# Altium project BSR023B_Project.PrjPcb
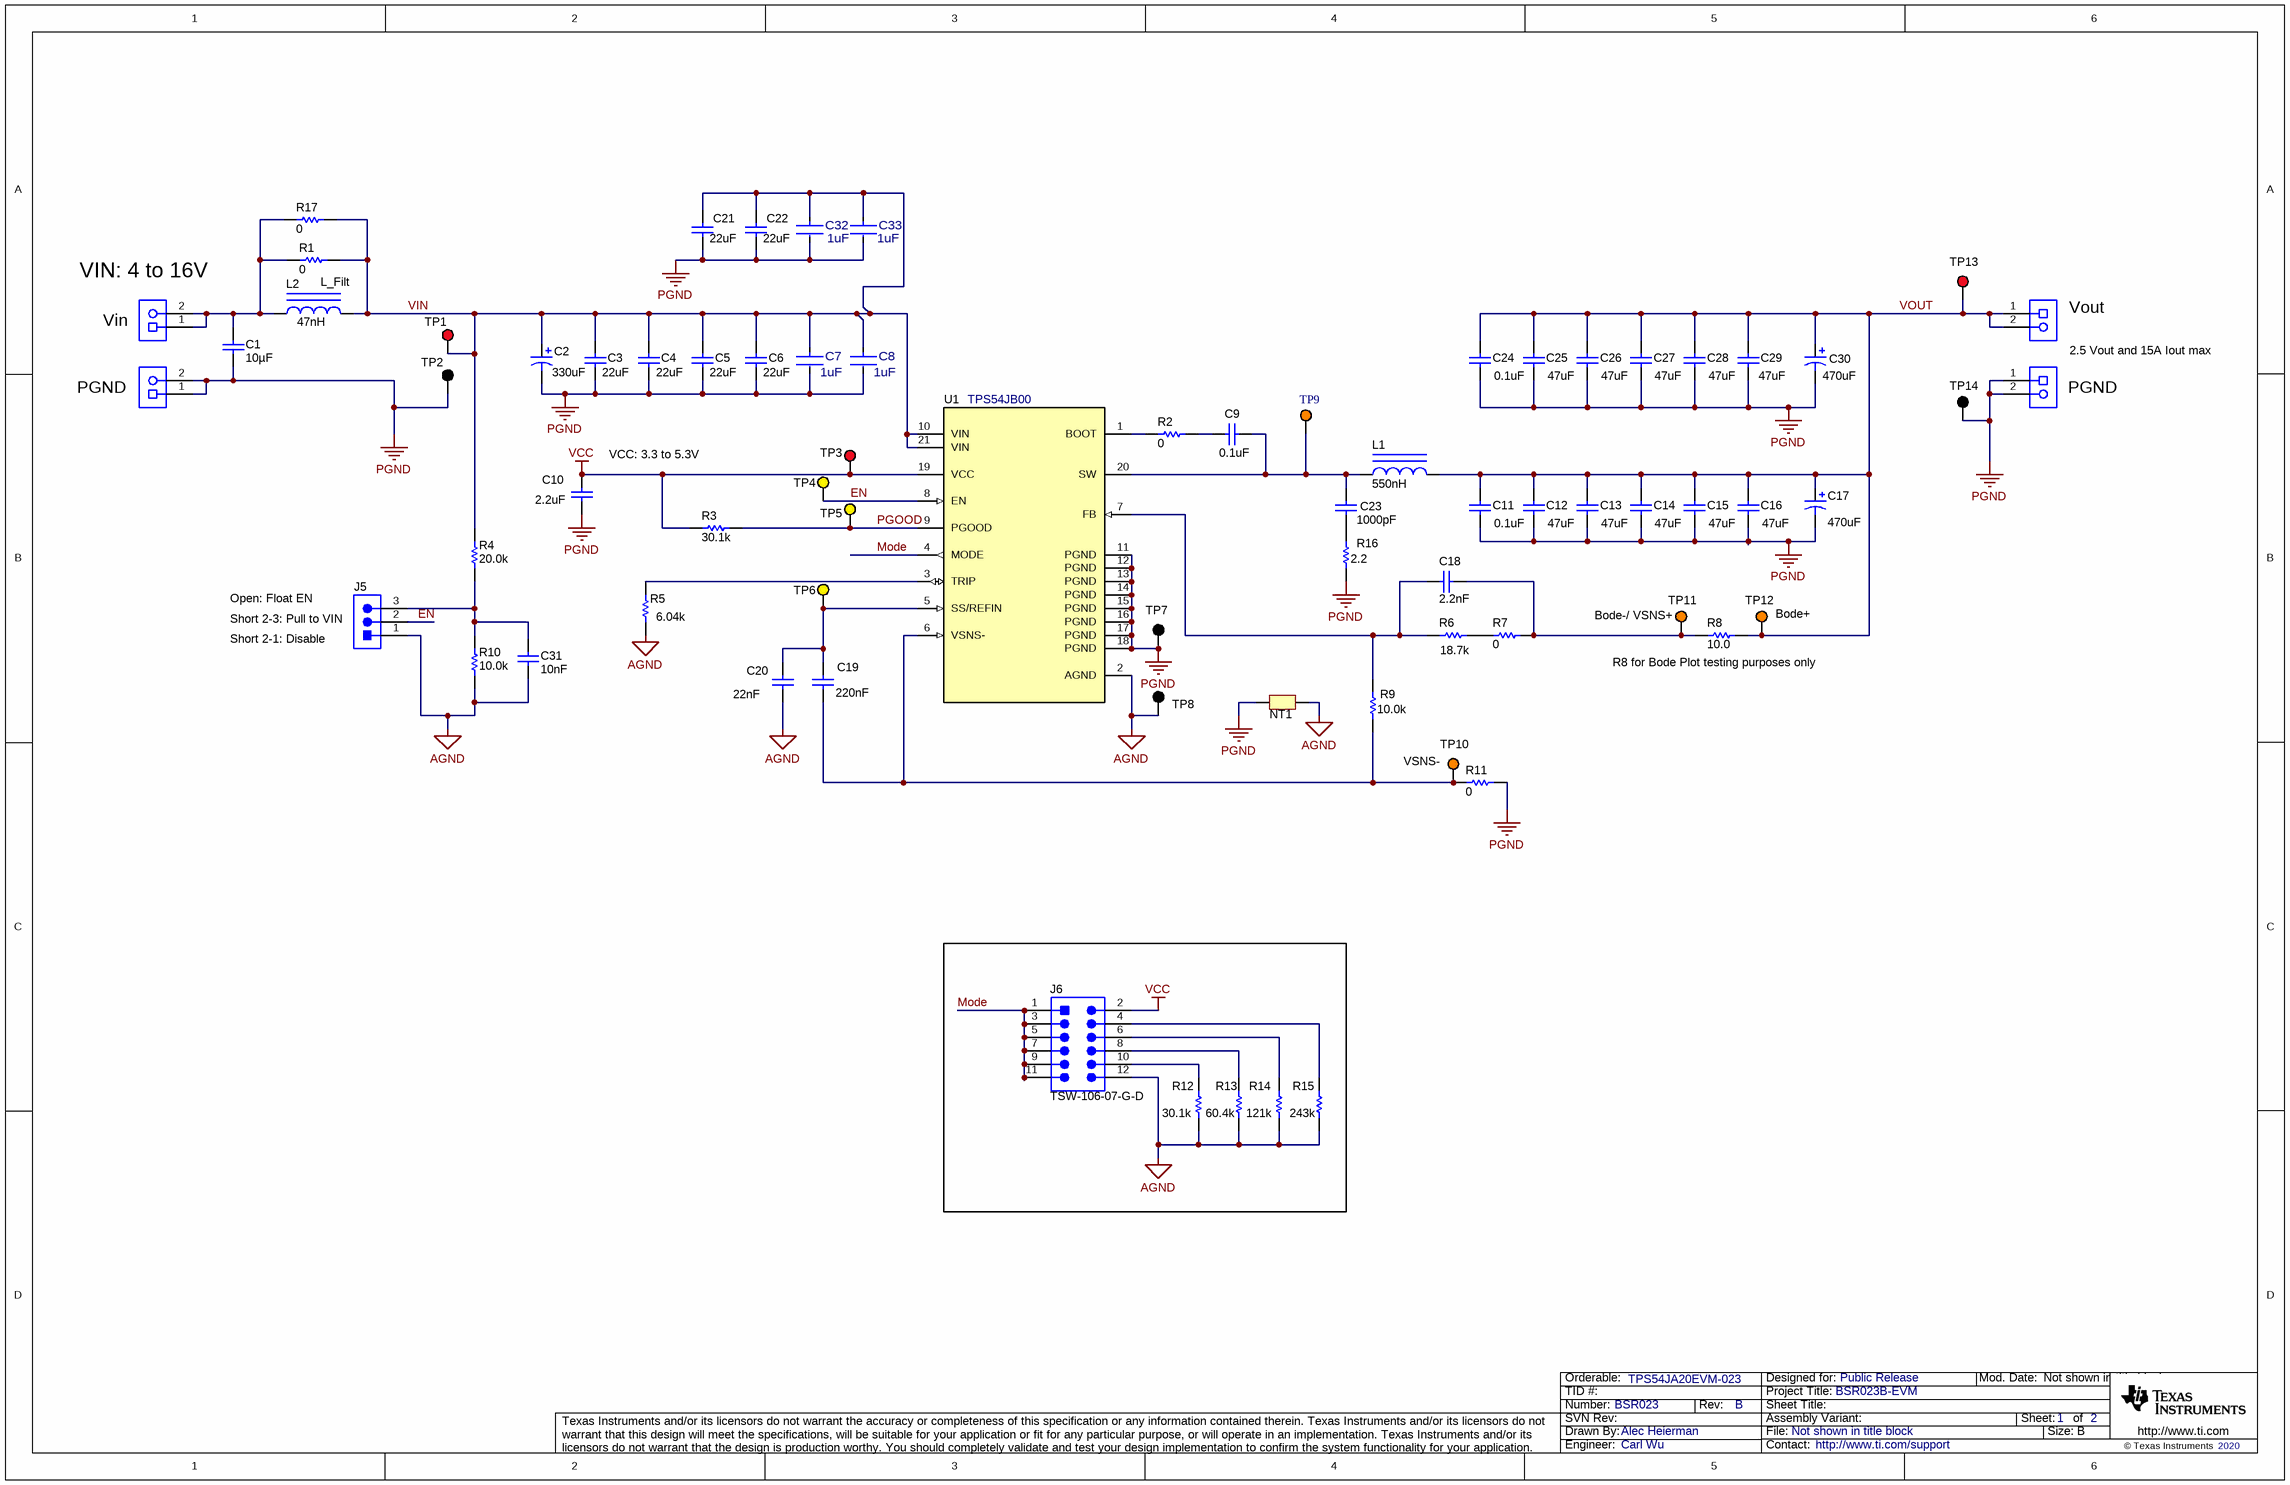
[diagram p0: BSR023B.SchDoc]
CopyrightYear: 2020; EVM_orderable: TPS54JA20EVM-023; PCB_Layout: David Daniels/Alec Heierman; PCB_Rev: B; PRJ_Customer: Public Release; PRJ_Engineer: Carl Wu; PRJ_Number: BSR023; PRJ_Title: BSR023B-EVM; SCH_Rev: B; TechSupport: http://www.ti.com/support
2 sheets, 96 parts. Net scope: global (net labels, ports and power ports of the same name join across sheets).
Board file: BSR023B.PcbDoc
Sheets:
  BSR023B.SchDoc
  BSR023B_Hardware.SchDoc

## Sheet BSR023B.SchDoc
size 431 x 279 mm; Date: Not shown in title block; ApprovedBy: Not shown in title block; CheckedBy: Not shown in title block; Author: Not shown in title block; CompanyName: Not shown in title block; DrawnBy: Alec Heierman; Engineer: Not shown in title block; Organization: Not shown in title block; Address1: Not shown in title block; Address2: Not shown in title block; Address3: Not shown in title block; Address4: Not shown in title block; DocumentNumber: 1; Revision: Use project parameter SCH_Rev; SheetNumber: 1; SheetTotal: 2; PageSetup: Record=PageOptions¦CenterHorizontal=True¦CenterVertical=True¦PrintScale=1.00¦XCorrection=1.00¦YCorrection=1.00¦PrintKind=0¦BorderSize=5000000¦LeftOffset=0¦BottomOffset=0¦Orientation=2¦PaperLength=1000¦PaperWidth=1000¦Scale=100¦PaperSource=15¦PrintQuality=600¦MediaType=1¦DitherType=10¦PaperKind=Letter¦PrintScaleMode=1

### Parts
C1  Cap_F: 10µF  [0805_HV]  (hidden comment: GRM21BZ71E106KE15L)
C2  ValueDisplayed: 330uF  [SM_RADIAL_G]  (hidden comment: EEE-FC1E331P)
C3  ValueDisplayed: 22uF  [1206_190]  (hidden comment: GRM31CC81E226ME11L)
C4  ValueDisplayed: 22uF  [1206_190]  (hidden comment: GRM31CC81E226ME11L)
C5  ValueDisplayed: 22uF  [1206_190]  (hidden comment: GRM31CC81E226ME11L)
C6  ValueDisplayed: 22uF  [1206_190]  (hidden comment: GRM31CC81E226ME11L)
C7  1uF  [FP-GRM155C81E105KE11D_0402-IPC_A]
C8  1uF  [FP-GRM155C81E105KE11D_0402-IPC_A]
C9  Cap_F: 0.1uF  [0603]  (hidden comment: CGA3E2X7R1H104K080AA)
C10  ValueDisplayed: 2.2uF  [0603]  (hidden comment: GRM188R71A225KE15D)
C11  ValueDisplayed: 0.1uF  [0402]  (hidden comment: GRM155R70J104KA01D)
C12  ValueDisplayed: 47uF  [1206_180]  (hidden comment: GRM31CC80J476KE18L)
C13  ValueDisplayed: 47uF  [1206_180]  (hidden comment: GRM31CC80J476KE18L)
C14  ValueDisplayed: 47uF  [1206_180]  (hidden comment: GRM31CC80J476KE18L)
C15  ValueDisplayed: 47uF  [1206_180]  (hidden comment: GRM31CC80J476KE18L)
C16  ValueDisplayed: 47uF  [1206_180]  (hidden comment: GRM31CC80J476KE18L)
C17  ValueDisplayed: 470uF  [7343-40]  (hidden comment: 6TPF470MAH)
C18  Cap_F: 2.2nF  [0603]  (hidden comment: C0603X222K5RACTU)
C19  Cap_F: 220nF  [0603]  (hidden comment: C1608X7R1C224K080AC)
C20  Cap_F: 22nF  [0603]  (hidden comment: C0603C223K4RACTU)
C21  ValueDisplayed: 22uF  [1206_190]  (hidden comment: GRM31CC81E226ME11L)
C22  ValueDisplayed: 22uF  [1206_190]  (hidden comment: GRM31CC81E226ME11L)
C23  value 1000pF  [0603]  (hidden comment: CL10C102JB8NNNC)
C24  ValueDisplayed: 0.1uF  [0402]  (hidden comment: GRM155R70J104KA01D)
C25  ValueDisplayed: 47uF  [1206_180]  (hidden comment: GRM31CC80J476KE18L)
C26  ValueDisplayed: 47uF  [1206_180]  (hidden comment: GRM31CC80J476KE18L)
C27  ValueDisplayed: 47uF  [1206_180]  (hidden comment: GRM31CC80J476KE18L)
C28  ValueDisplayed: 47uF  [1206_180]  (hidden comment: GRM31CC80J476KE18L)
C29  ValueDisplayed: 47uF  [1206_180]  (hidden comment: GRM31CC80J476KE18L)
C30  ValueDisplayed: 470uF  [7343-40]  (hidden comment: 6TPF470MAH)
C31  Cap_F: 10nF  [0603]  (hidden comment: 885012206040)
C32  1uF  [FP-GRM155C81E105KE11D_0402-IPC_A]
C33  1uF  [FP-GRM155C81E105KE11D_0402-IPC_A]
J1  ED120/2DS  [On-Shore_ED120_2DS]  (value not drawn)
J2  ED120/2DS  [On-Shore_ED120_2DS]  (value not drawn)
J3  ED120/2DS  [On-Shore_ED120_2DS]  (value not drawn)
J4  ED120/2DS  [On-Shore_ED120_2DS]  (value not drawn)
J5  (no value)  [Samtec_HTSW-103-07-G-S]
J6  TSW-106-07-G-D  [TSW-106-07-G-D]
L1  ValueDisplayed: 550nH  [XAL7070]  (hidden comment: XAL7070-551MEB)
L2  L_Filt  ValueDisplayed: 47nH  [0805CS]
NT1  Net-Tie  [NetTie_0402]  (value not drawn)  (net tie, no BOM)
R1  ValueDisplayed: 0  [5108]  (hidden comment: 5108)
R2  ValueDisplayed: 0  [0603]  (hidden comment: RMCF0603ZT0R00)
R3  ValueDisplayed: 30.1k  [0603]  (hidden comment: CRCW060330K1FKEA)
R4  ValueDisplayed: 20.0k  [0603]  (hidden comment: RT0603BRD0720KL)
R5  ValueDisplayed: 6.04k  [0603]  (hidden comment: CRCW06036K04FKEA)
R6  ValueDisplayed: 18.7k  [0603]  (hidden comment: CRCW060318K7FKEA)
R7  ValueDisplayed: 0  [0603]  (hidden comment: RMCF0603ZT0R00)
R8  ValueDisplayed: 10.0  [0603]  (hidden comment: CRCW060310R0FKEA)
R9  ValueDisplayed: 10.0k  [0603]  (hidden comment: CRCW060310K0FKEA)
R10  ValueDisplayed: 10.0k  [0603]  (hidden comment: CRCW060310K0FKEA)
R11  ValueDisplayed: 0  [0603]  (hidden comment: RMCF0603ZT0R00)
R12  ValueDisplayed: 30.1k  [0603]  (hidden comment: CRCW060330K1FKEA)
R13  ValueDisplayed: 60.4k  [0603]  (hidden comment: RC0603FR-0760K4L)
R14  ValueDisplayed: 121k  [0603]  (hidden comment: RC0603FR-07121KL)
R15  ValueDisplayed: 243k  [0603]  (hidden comment: CRCW0603243KFKEA)
R16  ValueDisplayed: 2.2  [1206]  (hidden comment: CRM1206-JW-2R2ELF)
R17  ValueDisplayed: 0  [5108]  (hidden comment: 5108)
TP1  VIN_SNS+  [Keystone5010]  (value not drawn)
TP2  VIN_SNS-  [Keystone5011]  (value not drawn)
TP3  VCC  [Keystone5010]  (value not drawn)
TP4  EN  [Keystone5009]  (value not drawn)
TP5  PGOOD  [Keystone5009]  (value not drawn)
TP6  SS/REFIN  [Keystone5009]  (value not drawn)
TP7  PGND  [Keystone5011]  (value not drawn)
TP8  AGND  [Keystone5011]  (value not drawn)
TP9  SW  [Keystone5008]  (value not drawn)
TP10  VSNS-  [Keystone5013]
TP11  BODE-  [Keystone5013]  (value not drawn)
TP12  Bode+  [Keystone5013]
TP13  VOUT+  [Keystone5010]  (value not drawn)
TP14  VOUT-  [Keystone5011]  (value not drawn)
U1  TPS54JB00  [RWW0021A]

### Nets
AGND: C20.2 C31.2 J5.1 J6.12 NT1.1 R5.1 R10.1 R12.1 R13.1 R14.1 R15.2 TP8.1 U1.2(AGND)
PGND: C1.2 C2.2(-) C3.2 C4.2 C5.2 C6.2 C7.2 C8.2 C10.2 C11.2 C12.2 C13.2 C14.2 C15.2 C16.2 C17.2(-) C21.2 C22.2 C24.2 C25.2 C26.2 C27.2 C28.2 C29.2 C30.2(-) C32.2 C33.2 J2.1 J2.2 J4.1 J4.2 NT1.2 R11.1 R16.1 TP2.1 TP7.1 TP14.1 U1.11(PGND) U1.12(PGND) U1.13(PGND) U1.14(PGND) U1.15(PGND) U1.16(PGND) U1.17(PGND) U1.18(PGND)
VCC: C10.1 J6.2 R3.1 TP3.1 U1.19(VCC)
EN: J5.2 TP4.1 U1.8(EN)
Mode: J6.1 J6.3 J6.5 J6.7 J6.9 J6.11 U1.4(MODE)
PGOOD: R3.2 TP5.1 U1.9(PGOOD)
VIN: C2.1(+) C3.1 C4.1 C5.1 C6.1 C7.1 C8.1 C21.1 C22.1 C32.1 C33.1 L2.2 R1.2 R4.2 R17.2 TP1.1 U1.10(VIN) U1.21(VIN)
VOUT: C11.1 C12.1 C13.1 C14.1 C15.1 C16.1 C17.1(+) C24.1 C25.1 C26.1 C27.1 C28.1 C29.1 C30.1(+) J3.1 J3.2 L1.2 R8.1 TP12.1 TP13.1
NetC1_1: C1.1 J1.1 J1.2 L2.1 R1.1 R17.1
NetC9_1: C9.1 C23.1 L1.1 TP9.1 U1.20(SW)
NetC9_2: C9.2 R2.2
NetC18_1: C18.1 R7.2 R8.2 TP11.1
NetC18_2: C18.2 R6.1 R9.1 U1.7(FB)
NetC19_1: C19.1 C20.1 TP6.1 U1.5(SS/REFIN)
NetC19_2: C19.2 R9.2 R11.2 TP10.1 U1.6(VSNS-)
NetC23_2: C23.2 R16.2
NetC31_1: C31.1 J5.3 R4.1 R10.2
NetJ6_4: J6.4 R15.1
NetJ6_6: J6.6 R14.2
NetJ6_8: J6.8 R13.2
NetJ6_10: J6.10 R12.2
NetR2_1: R2.1 U1.1(BOOT)
NetR5_2: R5.2 U1.3(TRIP)
NetR6_2: R6.2 R7.1

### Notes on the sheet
- (near J1) VIN: 4 to 16V
- (near J3) Vout
- (near J1) Vin
- 2.5 Vout and 15A Iout max
- PGND
- (near C10) VCC: 3.3 to 5.3V
- (near J5) Short 2-1: Disable
- Open: Float EN
- (near J5) Short 2-3: Pull to VIN
- (near TP11) Bode-/ VSNS+
- R8 for Bode Plot testing purposes only

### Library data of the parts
C1 = CMP-0008378-2: CAP, CERM, 10 uF, 25 V, +/- 10%, X7R, 0805; Manufacturer: MuRata; TaMin_C: -55°C; Polarized: N; SizeAreaWB_mm2: 6.75; Value1: Unknown; U/M: EA; Value: 10uF; TaMax_C: 125°C; SizeZ_mm: 1.45; SizeX_mm: 2; SizeY_mm: 1.25; Cap_Case: 0805; Value2: 25V; SizeArea_mm2: 2.5; AEC Category: Q200
C2 = CMP-0010657-1: CAP, AL, 330 uF, 25 V, +/- 20%, 0.15 ohm, SMD; Manufacturer: Panasonic; TaMin_C: -40°C; ESR_ohm: 0.15; Polarized: Y; SizeAreaWB_mm2: 172.2; U/M: EA; Value: 330uF; TaMax_C: 105°C; SizeZ_mm: 10.2; SizeX_mm: 12; SizeY_mm: 10.3; Cap_Case: G; Value2: 25V; SizeArea_mm2: 123.6; CompType: Capacitor; Cap_F: 330µF; IRMS_A: 670mA; AEC Category: Q200
C3-C6 C21 C22 = CMP-0008928-3: CAP, CERM, 22 uF, 25 V, +/- 20%, X6S, 1206_190; Manufacturer: MuRata; TaMin_C: -55°C; Polarized: N; SizeAreaWB_mm2: 10.92; Value1: Unknown; U/M: EA; Value: 22uF; TaMax_C: 105°C; SizeZ_mm: 1.9; SizeX_mm: 3.2; SizeY_mm: 1.6; Cap_Case: 1206; Value2: 25V; SizeArea_mm2: 5.12; Cap_F: 22µF; AEC Category: Q200
C7 C8 C32 C33 = CMP-0086485-1: CAP CER 1UF 25V X6S 0402; Manufacturer: Murata; PartNumber: GRM155C81E105KE11D; AEC Qualified: No; Cap_F: 1µF; Tolerance_%: 10%; TempCo: 22%; SizeZ_mm: 0.6mm; Symbol Name: SYM-GRM155C81E105KE11D
C9 = CMP-0007078-4: CAP, CERM, 0.1 uF, 50 V, +/- 10%, X7R, AEC-Q200 Grade 1, 0603; Manufacturer: TDK; TaMin_C: -55°C; ESR_ohm: 0.0296; Polarized: N; SizeAreaWB_mm2: 4.68; Value1: 0.0296 ohm; U/M: EA; Value: 0.1uF; TaMax_C: 125°C; SizeZ_mm: 1; SizeX_mm: 1.6; SizeY_mm: 0.8; Value2: 50V; SizeArea_mm2: 1.28; AEC Qualified: Y; IRMS_A: 971.99mA; AEC Category: Q200
C10 = CMP-0007370-4: CAP, CERM, 2.2 uF, 10 V, +/- 10%, X7R, 0603; Manufacturer: MuRata; Polarized: N; Value: 2.2uF; U/M: EA; Cap_F: 2.2µF; ESR_ohm: 9m; Value1: 0.009 ohm; VDC_V: 10V; TaMin_C: -55°C; TaMax_C: 125°C; SizeArea_mm2: 1.28; SizeAreaWB_mm2: 4.68; SizeX_mm: 1.6; SizeY_mm: 0.8; SizeZ_mm: 1; AEC Category: Q200
C11 C24 = CMP-0006623-2: CAP, CERM, 0.1 uF, 6.3 V, +/- 10%, X7R, 0402; Manufacturer: MuRata; TaMin_C: -55°C; Polarized: N; SizeAreaWB_mm2: 3; Value1: Unknown; U/M: EA; Value: 0.1uF; TaMax_C: 125°C; SizeZ_mm: 0.6; SizeX_mm: 1; SizeY_mm: 0.5; Value2: 6.3V; Cap_F: 100nF; AEC Category: Q200
C12-C16 C25-C29 = CMP-0008926-3: CAP, CERM, 47 uF, 6.3 V, +/- 10%, X6S, 1206; Manufacturer: MuRata; TaMin_C: -55°C; Polarized: N; SizeAreaWB_mm2: 10.92; Value1: Unknown; U/M: EA; Value: 47uF; TaMax_C: 105°C; SizeZ_mm: 1.8; SizeX_mm: 3.2; SizeY_mm: 1.6; Cap_Case: 1206; Value2: 6.3V; SizeArea_mm2: 5.12; Cap_F: 47µF; AEC Category: Q200
C17 C30 = CMP-0012642-3: CAP, Tantalum Polymer, 470 uF, 6.3 V, +/- 20%, 0.01 ohm, 7343-40 SMD; Manufacturer: Panasonic; TaMin_C: -55°C; ESR_ohm: 0.01; Polarized: Y; SizeAreaWB_mm2: 58.59; Value: 470uF; TaMax_C: 105°C; SizeZ_mm: 4; SizeX_mm: 7.3; SizeY_mm: 4.3; Cap_Case: D4; Value2: 6.3V; SizeArea_mm2: 31.39; CompType: Capacitor; AEC Qualified: N; Cap_F: 470µF; IRMS_A: 4.4A; AEC Category: Q200
C18 = CMP-0006983-4: CAP, CERM, 2200 pF, 50 V, +/- 10%, X7R, 0603; Manufacturer: Kemet; TaMin_C: -55°C; Polarized: N; SizeAreaWB_mm2: 4.68; Value1: Unknown; U/M: EA; Value: 2200pF; TaMax_C: 125°C; SizeZ_mm: 1; SizeX_mm: 1.6; SizeY_mm: 0.8; Value2: 50V; SizeArea_mm2: 1.28; AEC Category: Q200
C19 = CMP-0007038-5: CAP, CERM, 0.22 uF, 16 V, +/- 10%, X7R, 0603; Manufacturer: TDK; TaMin_C: -55°C; ESR_ohm: 0.0125; Polarized: N; SizeAreaWB_mm2: 4.68; Value1: 0.0125 ohm; U/M: EA; Value: 0.22uF; TaMax_C: 125°C; SizeZ_mm: 1; SizeX_mm: 1.6; SizeY_mm: 0.8; Value2: 16V; SizeArea_mm2: 1.28; AEC Category: Q200
C20 = CMP-0006900-4: CAP, CERM, 0.022 uF, 16 V, +/- 10%, X7R, 0603; Manufacturer: Kemet; TaMin_C: -55°C; Polarized: N; SizeAreaWB_mm2: 4.68; Value1: Unknown; U/M: EA; TaMax_C: 125°C; SizeZ_mm: 1; SizeX_mm: 1.6; SizeY_mm: 0.8; Value2: 16V; SizeArea_mm2: 1.28; AEC Category: Q200
C23 = CMP-0007114-5: CAP, CERM, 1000 pF, 50 V, +/- 5%, X7R, 0603; Manufacturer: Samsung Electro-Mechanics; TaMin_C: -55°C; Polarized: N; SizeAreaWB_mm2: 4.68; Value1: Unknown; U/M: EA; TaMax_C: 125°C; SizeZ_mm: 1; SizeX_mm: 1.6; SizeY_mm: 0.8; Value2: 50V; SizeArea_mm2: 1.28; Cap_F: 1nF; AEC Category: Q200
C31 = CMP-0006828-4: CAP, CERM, 0.01 uF, 16 V, +/- 10%, X7R, 0603; Manufacturer: Wurth Elektronik; TaMin_C: -55°C; Polarized: N; SizeAreaWB_mm2: 4.68; Value1: Unknown; U/M: EA; Value: 0.01uF; TaMax_C: 125°C; SizeZ_mm: 1; SizeX_mm: 1.6; SizeY_mm: 0.8; Value2: 16V; SizeArea_mm2: 1.28; AEC Category: Q200
J1-J4 = CMP-0074910-1: Terminal Block, 5.08 mm, 2x1, Brass, TH; Manufacturer: On-Shore Technology; Cert_VDE: Y; CNHeader: False; Current_A: 15A; Green_Lifecycle: Not Set; Shrouded: N; Gender: Female; Green_REACh: Incomplete; Voltage_V: 300V; Row_Count: 1; Pitch_mm: 5.08; CT: True
J5 = CMP-0075484-1: Header, 100mil, 3x1, Gold, TH; PartNumber: HTSW-103-07-G-S; Manufacturer: Samtec; CNHeader: True; CT: False; Green_Lifecycle: Active; Green_REACh: Passed
J6 = CMP-0075412-2: Header, 100mil, 6x2, Gold, TH; Manufacturer: Samtec; Pitch_mm: 2.54; Gender: Male; Shrouded: N; Row_Count: 2; Current_A: 6.3A; Voltage_V: 550V; Cert_CSA: Y; Green_Lifecycle: Active; Green_REACh: Passed
L1 = CMP-0061054-1: Inductor, Shielded, Composite, 550 nH, 29 A, 0.00142 ohm, SMD; Manufacturer: Coilcraft; Value: 550nH; Imax_A: 29A; Irms: 29A @ 40C rise; Isat: 43A @ 30% inductance drop; DCR_ohm: 1.42m; AEC Category: Q200; SizeAreaWB_mm2: 87.4; SizeArea_mm2: 54; SizeX_mm: 7.2; SizeY_mm: 7.5; SizeZ_mm: 7; Green_Lifecycle: Not Set; Green_REACh: Incomplete
L2 = CMP-0060183-1: Inductor, Wirewound, Ceramic, 47 nH, 0.5 A, 0.31 ohm, SMD; Manufacturer: Coilcraft; PartNumber: 0805CS-470XJLB; Irms: 0.5A @ 15C rise; Green_Lifecycle: Not Set; SizeAreaWB_mm2: 8.9817; DCR_ohm: 0.31; Green_REACh: Incomplete; Value: 47nH; Imax_A: 500mA; SizeZ_mm: 1.52; SizeX_mm: 2.29; SizeY_mm: 1.73; Value2: 0.5A; SizeArea_mm2: 3.9617; AEC Category: Q200
NT1 = CMP-0078142-3: Single point connection between nets.
R1 R17 = CMP-0016567-2: RES, 0, 1%, 0.5 W, 1206; Manufacturer: Keystone; Power_W: 500mW; TempCo: ppm/C; U/M: EA; Value: 0; SizeX_mm: 3.05; SizeY_mm: 1.7; SizeZ_mm: 0.84; Value2: 0.5W; SizeArea_mm2: 5.185; AEC Qualified: N; AEC Category: Q200
R2 R7 R11 = CMP-0023343-3: RES, 0, 1%, 0.1 W, AEC-Q200 Grade 0, 0603; Manufacturer: Stackpole Electronics Inc; Value: 0; U/M: EA; Power_W: 100mW; Value2: 0.1W; TempCo: ppm/C; AEC Category: Q200; AEC Qualified: Y; SizeArea_mm2: 1.28; SizeX_mm: 1.6; SizeY_mm: 0.8; SizeZ_mm: 1
R3 R12 = CMP-0022324-4: RES, 30.1 k, 1%, 0.1 W, AEC-Q200 Grade 0, 0603; Manufacturer: Vishay-Dale; Power_W: 100mW; TempCo: 100 ppm/C; Value_Code: 30k1; Value: 30.1k; EIA_Code: E96; SizeX_mm: 1.6; SizeY_mm: 0.8; SizeZ_mm: 1; Value2: 0.1W; SizeArea_mm2: 1.28; AEC Qualified: Y; VDC_V: 75V; AEC Category: Q200; AEC Grade: 0
R4 = CMP-0023931-3: RES, 20.0 k, 0.1%, 0.1 W, 0603; Manufacturer: Yageo America; Value: 20.0k; U/M: EA; Res_ohm: 20k; Value_Code: 20k0; Power_W: 100mW; Value2: 0.1W; VDC_V: 75V; TempCo: 25 ppm/C; EIA_Code: E192; AEC Category: Q200; SizeArea_mm2: 1.28; SizeX_mm: 1.6; SizeY_mm: 0.8; SizeZ_mm: 1
R5 = CMP-0022558-4: RES, 6.04 k, 1%, 0.1 W, AEC-Q200 Grade 0, 0603; Manufacturer: Vishay-Dale; CompType: Resistor; Value: 6.04k; Value_Code: 6k04; Power_W: 100mW; Value2: 0.1W; VDC_V: 75V; TempCo: 100 ppm/C; SizeArea_mm2: 1.28; SizeX_mm: 1.6; SizeY_mm: 0.8; SizeZ_mm: 1; EIA_Code: E96; AEC Category: Q200; AEC Qualified: Y; AEC Grade: 0
R6 = CMP-0022098-4: RES, 18.7 k, 1%, 0.1 W, AEC-Q200 Grade 0, 0603; Manufacturer: Vishay-Dale; Value: 18.7k; Value_Code: 18k7; Power_W: 100mW; Value2: 0.1W; VDC_V: 75V; TempCo: 100 ppm/C; SizeArea_mm2: 1.28; SizeX_mm: 1.6; SizeY_mm: 0.8; SizeZ_mm: 1; EIA_Code: E96; AEC Category: Q200; AEC Qualified: Y; AEC Grade: 0
R8 = CMP-0022003-4: RES, 10.0, 1%, 0.1 W, AEC-Q200 Grade 0, 0603; Manufacturer: Vishay-Dale; Value: 10.0; Res_ohm: 10; Value_Code: 10R0; Power_W: 100mW; Value2: 0.1W; VDC_V: 75V; TempCo: 100 ppm/C; EIA_Code: E96; AEC Category: Q200; AEC Qualified: Y; AEC Grade: 0; SizeArea_mm2: 1.28; SizeX_mm: 1.6; SizeY_mm: 0.8; SizeZ_mm: 1
R9 R10 = CMP-0021998-4: RES, 10.0 k, 1%, 0.1 W, AEC-Q200 Grade 0, 0603; Manufacturer: Vishay-Dale; Value: 10.0k; Res_ohm: 10k; Value_Code: 10k0; Power_W: 100mW; Value2: 0.1W; VDC_V: 75V; TempCo: 100 ppm/C; EIA_Code: E96; AEC Category: Q200; AEC Qualified: Y; AEC Grade: 0; SizeArea_mm2: 1.28; SizeX_mm: 1.6; SizeY_mm: 0.8; SizeZ_mm: 1
R13 = CMP-0023212-5: RES, 60.4 k, 1%, 0.1 W, 0603; Manufacturer: Yageo; Power_W: 100mW; TempCo: 100 ppm/C; Value_Code: 60k4; Value: 60.4k; EIA_Code: E96; SizeX_mm: 1.6; SizeY_mm: 0.8; SizeZ_mm: 1; Value2: 0.1W; SizeArea_mm2: 1.28; AEC Qualified: N; VDC_V: 75V; AEC Category: Q200; SizeAreaWB_mm2: 4.68
R14 = CMP-0022770-4: RES, 121 k, 1%, 0.1 W, 0603; Manufacturer: Yageo; Power_W: 100mW; TempCo: 100 ppm/C; Value: 121k; EIA_Code: E96; SizeX_mm: 1.6; SizeY_mm: 0.8; SizeZ_mm: 1; Value2: 0.1W; SizeArea_mm2: 1.28; AEC Qualified: N; VDC_V: 75V; AEC Category: Q200; SizeAreaWB_mm2: 4.68
R15 = CMP-0022232-4: RES, 243 k, 1%, 0.1 W, AEC-Q200 Grade 0, 0603; Manufacturer: Vishay-Dale; Value: 243k; Power_W: 100mW; Value2: 0.1W; VDC_V: 75V; TempCo: 100 ppm/C; SizeArea_mm2: 1.28; SizeX_mm: 1.6; SizeY_mm: 0.8; SizeZ_mm: 1; EIA_Code: E96; AEC Category: Q200; AEC Qualified: Y; AEC Grade: 0
R16 = CMP-0018746-2: RES, 2.2, 5%, 0.5 W, 1206; Manufacturer: Bourns; Value: 2.2; Value_Code: 2R20; Power_W: 500mW; Value2: 0.5W; VDC_V: 1V; TempCo: 100 ppm/C; EIA_Code: E24; U/M: EA; AEC Category: Q200; SizeArea_mm2: 5.12; SizeX_mm: 3.2; SizeY_mm: 1.6; SizeZ_mm: 1.35
TP1 TP3 TP13 = CMP-0055147-1: Test Point, Multipurpose, Red, TH; Manufacturer: Keystone; ContactFinish: Silver; CNHeader: FALSE; CT: TRUE; Green_Lifecycle: Active; Green_REACh: Passed
TP2 TP7 TP8 TP14 = CMP-0055148-1: Test Point, Multipurpose, Black, TH; Manufacturer: Keystone; ContactFinish: Silver; CNHeader: FALSE; CT: TRUE; Green_Lifecycle: Active; Green_REACh: Passed
TP4-TP6 = CMP-0055146-1: Test Point, Compact, Yellow, TH; Manufacturer: Keystone; ContactFinish: Silver; CNHeader: FALSE; CT: TRUE; Green_Lifecycle: Active; Green_REACh: Passed
TP9 = CMP-0055145-1: Test Point, Compact, Orange, TH; Manufacturer: Keystone; CNHeader: FALSE; Green_Lifecycle: Active; Green_REACh: Passed; ContactFinish: Silver; CT: TRUE
TP10-TP12 = CMP-0055150-1: Test Point, Multipurpose, Orange, TH; Manufacturer: Keystone; ContactFinish: Silver; CNHeader: FALSE; CT: TRUE; Green_Lifecycle: Active; Green_REACh: Passed
U1 = CMP-0079178-4: 4-V to 16-V Input, 20-A Single Synchronous Step-Down Converter, RWW0021A (VQFN-HR-21); Alternate PartNumber: TPS54JB00RWWR; Alternate Manufacturer: Texas Instruments; PartNumber: TPS54JB00RWWT; SizeAreaWB_mm2: 20; SizeZ_mm: 1; SizeX_mm: 3; SizeY_mm: 4; SizeArea_mm2: 12; CompType: IC; AEC Qualified: N; AEC Category: Q200

## Sheet BSR023B_Hardware.SchDoc
size 431 x 279 mm; Date: Not shown in title block; ApprovedBy: Not shown in title block; CheckedBy: Not shown in title block; Author: Not shown in title block; CompanyName: Not shown in title block; DrawnBy: David Daniels/Alec Heierman; Engineer: Not shown in title block; Organization: Not shown in title block; Address1: Not shown in title block; Address2: Not shown in title block; Address3: Not shown in title block; Address4: Not shown in title block; DocumentNumber: 2; Revision: Use project parameter SCH_Rev; SheetNumber: 2; SheetTotal: 2; PageSetup: Record=PageOptions¦CenterHorizontal=True¦CenterVertical=True¦PrintScale=1.00¦XCorrection=1.00¦YCorrection=1.00¦PrintKind=0¦BorderSize=5000000¦LeftOffset=0¦BottomOffset=0¦Orientation=2¦PaperLength=1000¦PaperWidth=1000¦Scale=100¦PaperSource=15¦PrintQuality=600¦MediaType=1¦DitherType=10¦PaperKind=Letter¦PrintScaleMode=1
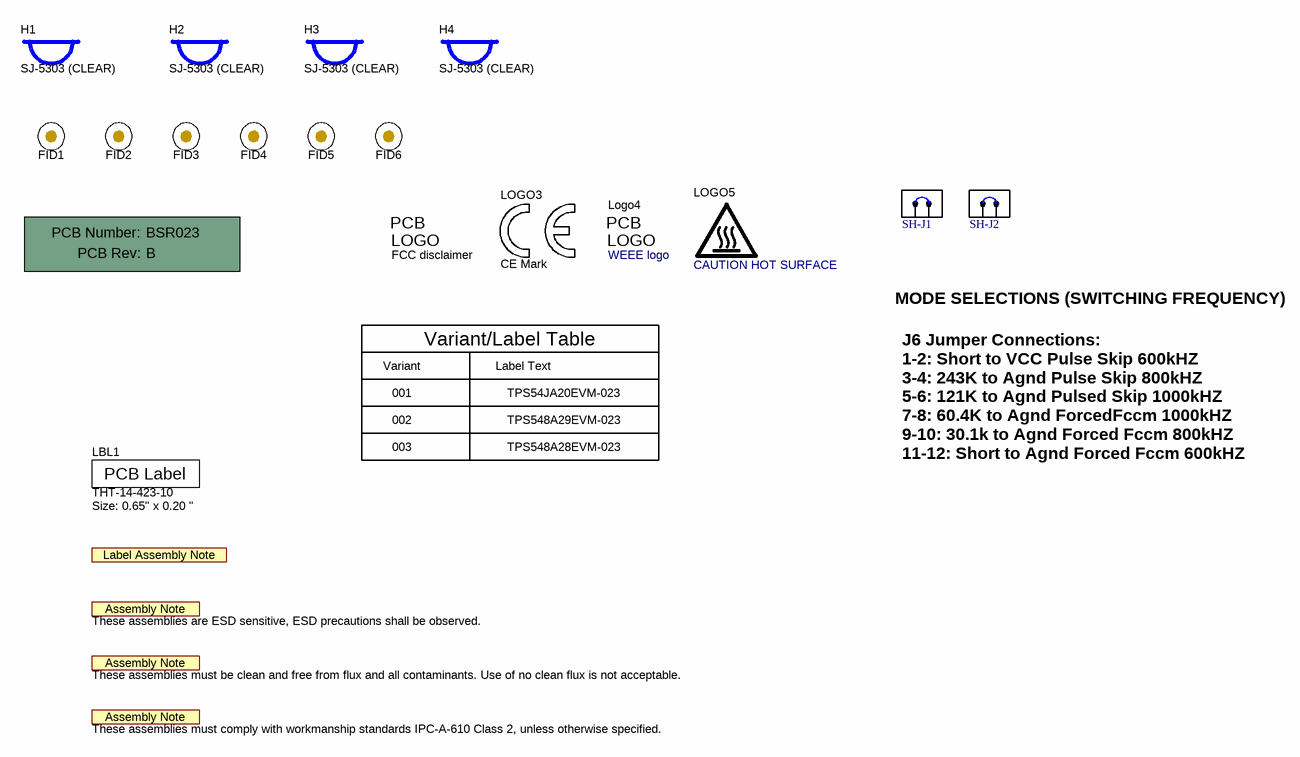
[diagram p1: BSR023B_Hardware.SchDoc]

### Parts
!PCB1  Printed Circuit Board  (value not drawn)  (mechanical)
FID1  Fiducial  [Fiducial10-20]  (value not drawn)
FID2  Fiducial  [Fiducial10-20]  (value not drawn)
FID3  Fiducial  [Fiducial10-20]  (value not drawn)
FID4  Fiducial  [Fiducial10-20]  (value not drawn)
FID5  Fiducial  [Fiducial10-20]  (value not drawn)
FID6  Fiducial  [Fiducial10-20]  (value not drawn)
H1  SJ-5303 (CLEAR)  [Bumpon_SJ5003Transparent]
H2  SJ-5303 (CLEAR)  [Bumpon_SJ5003Transparent]
H3  SJ-5303 (CLEAR)  [Bumpon_SJ5003Transparent]
H4  SJ-5303 (CLEAR)  [Bumpon_SJ5003Transparent]
LBL1  THT-14-423-10  Note: Size: 0.65" x 0.20 "  [Label_650x200]
Logo2  FCC disclaimer  [FCC_disclaimer]  (no BOM)
LOGO3  CE Mark  [CE_Mark_5mm]  (no BOM)
Logo4  WEEE logo  [WEEE_Minimum]  (no BOM)
LOGO5  CAUTION HOT SURFACE  [IEC_HotSurface_Small]  (no BOM)
SH-J1  SNT-100-BK-G  [SNT-100-BK-G]  (value not drawn)
SH-J2  SNT-100-BK-G  [SNT-100-BK-G]  (value not drawn)
ZZ1  This Assembly Note is for PCB labels only  [AssemblyNoteLabel]  (value not drawn)  (no BOM)
ZZ2  These assemblies are ESD sensitive, ESD precautions shall be observed.  [AssemblyNote]  (no BOM)
ZZ3  These assemblies must be clean and free from flux and all contaminants. Use of no clean flux is not acceptable.  [AssemblyNote]  (no BOM)
ZZ4  These assemblies must comply with workmanship standards IPC-A-610 Class 2, unless otherwise specified.  [AssemblyNote]  (no BOM)

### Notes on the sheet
- Variant/Label Table
- MODE SELECTIONS (SWITCHING FREQUENCY)
- Variant
- 001
- 002
- Label Text
- TPS54JA20EVM-023
- TPS548A29EVM-023
- 003
- TPS548A28EVM-023
- J6 Jumper Connections:
  1-2: Short to VCC Pulse Skip 600kHZ
  3-4: 243K to Agnd Pulse Skip 800kHZ
  5-6: 121K to Agnd Pulsed Skip 1000kHZ
  7-8: 60.4K to Agnd ForcedFccm 1000kHZ
  9-10: 30.1k to Agnd Forced Fccm 800kHZ
  11-12: Short to Agnd Forced Fccm 600kHZ

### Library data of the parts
!PCB1 = CMP-0003618-2: Manufacturer: Any; PartNumber: BSR023
FID1-FID6 = CMP-0077181-1: Fiducial mark.  There is nothing to buy or mount.
H1-H4 = CMP-0003620-1: Bumpon, Hemisphere, 0.44 X 0.20, Clear; Manufacturer: 3M
LBL1 = CMP-0003625-1: Thermal Transfer Printable Labels, 0.650" W x 0.200" H - 10,000 per roll; Manufacturer: Brady; CompType: Label
Logo2 = CMP-0074847-1: FCC_disclaimer; Library Reference: Logo
LOGO3 = CMP-0074844-1: SymbolCreator: a0412235
Logo4 = CMP-0074769-1
LOGO5 = CMP-0074837-1: IEC 61010-1 Hot Surface Warning; SymbolCreator: a0412235
SH-J1 SH-J2 = CMP-0003623-3: Shunt, 100mil, Gold plated, Black; Alternate PartNumber: 969102-0000-DA; Manufacturer: Samtec; Alternate Manufacturer: 3M; Value: 1x2; Note: You can "mate" this to a header by matching the designator.  i.e. use SH-J3 for header J3
ZZ1 = CMP-0003616-3
ZZ2 = CMP-0077236-1
ZZ3 = CMP-0077237-1
ZZ4 = CMP-0077238-1

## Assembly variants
001: not fitted C1 C3 C4 C15 C16 C17 C18 C23 C28 C29 C30 C31 C33 FID1 FID2 FID3 FID4 FID5 FID6 L2 R16; alternate parts L1 -> CMP-0061058-1, R5 -> CMP-0023155-5, U1 -> CMP-0860433-1, R6 -> CMP-0022090-4
002: not fitted C1 C3 C4 C14 C15 C16 C17 C18 C20 C23 C27 C28 C29 C30 C31 C33 FID1 FID2 FID3 FID4 FID5 FID6 L2 R16; alternate parts L1 -> CMP-0061058-1, R6 -> CMP-0022330-4, R5 -> CMP-0022449-4, C19 -> CMP-0007039-5, R7 -> CMP-0023343-3, U1 -> CMP-0750199-5
003: not fitted C1 C3 C4 C14 C15 C16 C17 C18 C20 C23 C27 C28 C29 C30 C31 C33 FID1 FID2 FID3 FID4 FID5 FID6 L2 R16; alternate parts L1 -> CMP-0061058-1, R6 -> CMP-0022330-4, R5 -> CMP-0022449-4, C19 -> CMP-0007039-5, R7 -> CMP-0023343-3, U1 -> CMP-0860432-1
004: not fitted C1 C12 C17 C20 C23 C25 C30 C31 L2 R16; alternate parts L1 -> CMP-0061058-1, R6 -> CMP-0022958-5, C18 -> CMP-0006751-1
005: not fitted C1 C12 C17 C18 C20 C23 C25 C30 C31 L2 R16; alternate parts L1 -> CMP-0061051-1, R6 -> CMP-0023251-5
006: not fitted C1 C12 C17 C18 C20 C23 C25 C30 C31 L2 R16; alternate parts L1 -> CMP-0061051-1, R6 -> CMP-0023251-5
